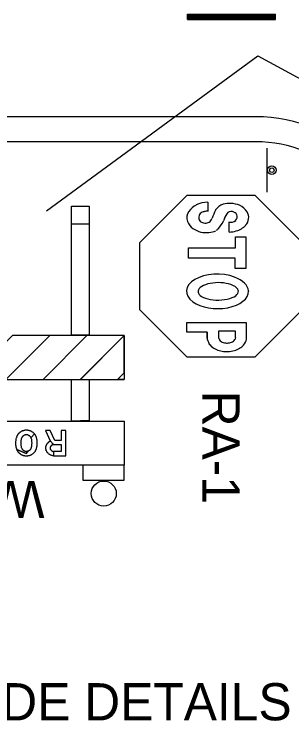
# Model space of a CAD drawing. Extents: x 1482 to 1692, y 225 to 494.
# Drawn here: x 1523.34 to 1536.77, y 348.19 to 382.4 of the extents above; entities that cross this region are included whole.
import ezdxf

# ---------------------------------------------------------------- set-up
doc = ezdxf.new("R2010")
doc.units = 0
doc.layers.add('Level 17', color=7, linetype='Continuous')
doc.layers.add('Level 2', color=7, linetype='Continuous')

msp = doc.modelspace()

# ---------------------------------------------------------------- linework, layer by layer
at = {"layer": 'Level 17'}
for p, q in [((1524.905, 372.882), (1535.123, 380.389)), ((1535.123, 380.389), (1542.24, 376.488)), ((1535.565, 375.918), (1535.565, 373.784)), ((1532.709, 373.304), (1532.709, 372.854)), ((1532.14, 373.162), (1532.142, 373.165)), ((1533.741, 371.848), (1533.741, 372.34)), ((1526.117, 372.257), (1526.968, 372.257)), ((1534.041, 371.086), (1534.041, 371.614)), ((1534.041, 371.614), (1534.544, 371.614)), ((1534.544, 371.614), (1534.544, 370.084)), ((1531.78, 370.588), (1531.78, 371.086)), ((1531.78, 371.086), (1534.041, 371.086)), ((1534.029, 370.588), (1531.78, 370.588)), ((1534.029, 370.084), (1534.029, 370.588)), ((1534.544, 370.084), (1534.029, 370.084)), ((1534.182, 369.026), (1534.186, 369.007)), ((1534.671, 369.007), (1534.672, 368.992)), ((1531.696, 367.003), (1531.696, 367.48)), ((1531.696, 367.48), (1534.57, 367.48)), ((1534.57, 367.48), (1534.57, 366.676)), ((1528.668, 366.838), (1528.668, 364.713)), ((1532.676, 367.003), (1531.696, 367.003)), ((1532.676, 367.003), (1532.676, 366.703)), ((1532.684, 366.716), (1532.676, 367.003)), ((1534.054, 367.06), (1533.219, 367.06)), ((1533.219, 367.06), (1533.219, 366.754)), ((1534.054, 367.06), (1533.219, 367.06)), ((1533.219, 367.06), (1533.219, 366.754)), ((1534.054, 366.748), (1534.054, 367.06)), ((1534.054, 366.748), (1534.054, 367.06)), ((1507.928, 364.713), (1528.668, 364.713)), ((1507.928, 362.695), (1528.668, 362.695)), ((1528.668, 362.695), (1528.668, 360.57)), ((1524.162, 361.903), (1524.327, 362.077)), ((1524.327, 362.077), (1524.162, 361.903)), ((1524.172, 361.874), (1524.162, 361.903)), ((1525.092, 361.739), (1525.247, 361.565)), ((1525.092, 361.739), (1525.247, 361.565)), ((1523.477, 361.323), (1523.93, 361.136)), ((1523.93, 361.136), (1523.477, 361.323)), ((1525.247, 361.565), (1525.256, 361.565)), ((1523.93, 361.136), (1524.018, 361.256)), ((1524.018, 361.256), (1523.93, 361.136)), ((1525.247, 361.236), (1525.247, 361.024)), ((1525.247, 361.236), (1525.247, 361.024)), ((1528.668, 360.57), (1507.928, 360.57))]:
    msp.add_line(p, q, dxfattribs=at)
for points in [[(1531.716, 365.791), (1529.422, 368.084), (1529.422, 371.352), (1531.716, 373.645), (1534.983, 373.645), (1537.275, 371.352), (1537.275, 368.084), (1534.983, 365.791)], [(1526.968, 366.86), (1526.117, 366.86), (1526.117, 373.108), (1526.968, 373.108)], [(1521.134, 364.713), (1522.938, 364.713), (1525.063, 366.838), (1523.259, 366.838)], [(1524.74, 364.713), (1526.544, 364.713), (1528.669, 366.838), (1526.865, 366.838)], [(1528.668, 364.713), (1528.346, 364.713), (1528.668, 365.035)], [(1526.968, 362.737), (1526.117, 362.695), (1526.117, 364.713), (1526.968, 364.713)], [(1528.668, 360.57), (1526.664, 360.57), (1526.664, 359.842), (1528.668, 359.842)]]:
    msp.add_lwpolyline(points, close=True, dxfattribs=at)
for points in [[(1525.062, 366.838), (1522.937, 364.713), (1524.74, 364.713), (1526.865, 366.838), (1525.062, 366.838)], [(1528.668, 366.838), (1526.543, 364.713), (1528.346, 364.713), (1528.668, 365.035), (1528.668, 366.838)], [(1523.477, 361.323), (1523.467, 361.352), (1523.457, 361.372), (1523.457, 361.401), (1523.448, 361.43), (1523.448, 361.449), (1523.438, 361.478), (1523.438, 361.497), (1523.428, 361.526), (1523.428, 361.555), (1523.428, 361.575), (1523.428, 361.603), (1523.428, 361.632), (1523.428, 361.652), (1523.428, 361.681), (1523.428, 361.7), (1523.428, 361.729), (1523.438, 361.758), (1523.438, 361.777), (1523.438, 361.806), (1523.448, 361.835), (1523.448, 361.855), (1523.457, 361.884), (1523.457, 361.893), (1523.467, 361.913), (1523.467, 361.932), (1523.477, 361.951), (1523.486, 361.961), (1523.486, 361.98), (1523.496, 361.999), (1523.506, 362.009), (1523.515, 362.028), (1523.525, 362.048), (1523.535, 362.057), (1523.544, 362.077), (1523.554, 362.086), (1523.564, 362.096), (1523.573, 362.115), (1523.593, 362.125), (1523.602, 362.135), (1523.612, 362.154), (1523.631, 362.164), (1523.641, 362.173), (1523.66, 362.183), (1523.67, 362.192), (1523.689, 362.202), (1523.699, 362.212), (1523.718, 362.222), (1523.738, 362.231), (1523.747, 362.231), (1523.766, 362.241), (1523.786, 362.25), (1523.805, 362.25), (1523.815, 362.26), (1523.834, 362.26), (1523.853, 362.26), (1523.873, 362.27), (1523.892, 362.27), (1523.902, 362.27), (1523.921, 362.27), (1523.94, 362.27), (1523.96, 362.27), (1523.979, 362.27), (1523.989, 362.27), (1524.008, 362.26), (1524.027, 362.26), (1524.047, 362.26), (1524.066, 362.25), (1524.076, 362.25), (1524.095, 362.241), (1524.114, 362.241), (1524.134, 362.231), (1524.143, 362.222), (1524.162, 362.212), (1524.182, 362.202), (1524.191, 362.192), (1524.211, 362.183), (1524.22, 362.173), (1524.239, 362.164), (1524.249, 362.154), (1524.259, 362.144), (1524.278, 362.135), (1524.288, 362.115), (1524.298, 362.106), (1524.307, 362.096), (1524.327, 362.077)], [(1524.327, 362.077), (1524.336, 362.067), (1524.346, 362.048), (1524.356, 362.038), (1524.365, 362.019), (1524.375, 361.999), (1524.375, 361.99), (1524.385, 361.971), (1524.394, 361.951), (1524.404, 361.932), (1524.404, 361.903), (1524.414, 361.884), (1524.423, 361.855), (1524.423, 361.826), (1524.433, 361.806), (1524.433, 361.777), (1524.433, 361.758), (1524.443, 361.729), (1524.443, 361.7), (1524.443, 361.681), (1524.443, 361.652), (1524.443, 361.623), (1524.443, 361.594), (1524.443, 361.575), (1524.443, 361.545), (1524.433, 361.516), (1524.433, 361.497), (1524.433, 361.468), (1524.423, 361.449), (1524.423, 361.42), (1524.414, 361.391), (1524.404, 361.372), (1524.404, 361.343), (1524.394, 361.323), (1524.385, 361.304), (1524.375, 361.285), (1524.375, 361.275), (1524.365, 361.256), (1524.356, 361.236), (1524.346, 361.227), (1524.336, 361.207), (1524.327, 361.198), (1524.307, 361.179), (1524.298, 361.169), (1524.288, 361.159), (1524.278, 361.14), (1524.259, 361.13), (1524.249, 361.12), (1524.239, 361.111), (1524.22, 361.101), (1524.211, 361.092), (1524.191, 361.082), (1524.182, 361.072), (1524.162, 361.062), (1524.143, 361.053), (1524.134, 361.043), (1524.114, 361.033), (1524.095, 361.033), (1524.076, 361.024), (1524.066, 361.024), (1524.047, 361.014), (1524.027, 361.014), (1524.008, 361.014), (1523.989, 361.005), (1523.979, 361.005), (1523.96, 361.005), (1523.94, 361.005), (1523.921, 361.005), (1523.902, 361.005), (1523.882, 361.005), (1523.873, 361.005), (1523.853, 361.014), (1523.834, 361.014), (1523.815, 361.014), (1523.795, 361.024), (1523.786, 361.033), (1523.766, 361.033), (1523.747, 361.043), (1523.738, 361.043), (1523.718, 361.053), (1523.699, 361.062), (1523.689, 361.072), (1523.67, 361.082), (1523.66, 361.092), (1523.641, 361.101), (1523.631, 361.111), (1523.612, 361.12), (1523.602, 361.14), (1523.593, 361.149), (1523.573, 361.159), (1523.564, 361.179), (1523.554, 361.188), (1523.544, 361.198), (1523.535, 361.217), (1523.525, 361.227), (1523.515, 361.246), (1523.506, 361.265), (1523.496, 361.275), (1523.486, 361.294), (1523.486, 361.314), (1523.477, 361.323)], [(1524.172, 361.874), (1524.162, 361.884), (1524.162, 361.903), (1524.153, 361.913), (1524.143, 361.922), (1524.134, 361.932), (1524.134, 361.942), (1524.124, 361.951), (1524.114, 361.961), (1524.105, 361.971), (1524.095, 361.98), (1524.085, 361.99), (1524.076, 361.99), (1524.056, 361.999), (1524.047, 362.009), (1524.037, 362.009), (1524.027, 362.019), (1524.018, 362.019), (1523.998, 362.028), (1523.989, 362.028), (1523.979, 362.028), (1523.96, 362.028), (1523.95, 362.028), (1523.94, 362.038), (1523.921, 362.038), (1523.911, 362.028), (1523.902, 362.028), (1523.882, 362.028), (1523.873, 362.028), (1523.863, 362.019), (1523.853, 362.019), (1523.834, 362.019), (1523.824, 362.009), (1523.815, 361.999), (1523.805, 361.999), (1523.795, 361.99), (1523.786, 361.98), (1523.776, 361.971), (1523.766, 361.971), (1523.757, 361.961), (1523.747, 361.951), (1523.738, 361.942), (1523.728, 361.922), (1523.718, 361.913), (1523.718, 361.903), (1523.709, 361.893), (1523.699, 361.884), (1523.699, 361.874), (1523.689, 361.845), (1523.689, 361.826), (1523.68, 361.806), (1523.68, 361.787), (1523.67, 361.758), (1523.67, 361.739), (1523.67, 361.719), (1523.67, 361.69), (1523.66, 361.671), (1523.66, 361.652), (1523.66, 361.623), (1523.66, 361.603), (1523.67, 361.584), (1523.67, 361.555), (1523.67, 361.536), (1523.67, 361.516), (1523.68, 361.488), (1523.68, 361.468), (1523.689, 361.449), (1523.689, 361.43), (1523.689, 361.42), (1523.699, 361.41), (1523.699, 361.401), (1523.709, 361.381), (1523.709, 361.372), (1523.718, 361.362), (1523.728, 361.352), (1523.738, 361.343), (1523.738, 361.333), (1523.747, 361.323), (1523.757, 361.314), (1523.766, 361.304), (1523.776, 361.294), (1523.786, 361.285), (1523.795, 361.285), (1523.805, 361.275), (1523.824, 361.265), (1523.834, 361.265), (1523.844, 361.256), (1523.853, 361.256), (1523.863, 361.246), (1523.882, 361.246), (1523.892, 361.246), (1523.902, 361.246), (1523.921, 361.246), (1523.931, 361.236), (1523.94, 361.236), (1523.96, 361.246), (1523.969, 361.246), (1523.979, 361.246), (1523.998, 361.246), (1524.008, 361.256), (1524.018, 361.256)], [(1525.247, 361.024), (1525.836, 361.024), (1525.836, 362.25), (1525.624, 362.25), (1525.624, 361.768), (1525.315, 361.768), (1525.092, 362.25), (1524.861, 362.25), (1525.092, 361.739)], [(1524.018, 361.256), (1524.027, 361.256), (1524.047, 361.265), (1524.056, 361.275), (1524.066, 361.275), (1524.076, 361.285), (1524.085, 361.294), (1524.095, 361.294), (1524.105, 361.304), (1524.114, 361.314), (1524.124, 361.323), (1524.134, 361.333), (1524.143, 361.343), (1524.143, 361.352), (1524.153, 361.362), (1524.162, 361.381), (1524.162, 361.391), (1524.172, 361.401), (1524.172, 361.41), (1524.182, 361.43), (1524.182, 361.439), (1524.182, 361.449), (1524.191, 361.478), (1524.191, 361.497), (1524.201, 361.516), (1524.201, 361.536), (1524.201, 361.565), (1524.201, 361.584), (1524.201, 361.603), (1524.211, 361.632), (1524.211, 361.652), (1524.201, 361.681), (1524.201, 361.7), (1524.201, 361.719), (1524.201, 361.748), (1524.191, 361.768), (1524.191, 361.787), (1524.191, 361.806), (1524.182, 361.835), (1524.172, 361.855), (1524.172, 361.874)], [(1525.256, 361.024), (1525.237, 361.024), (1525.218, 361.024), (1525.208, 361.024), (1525.189, 361.033), (1525.17, 361.033), (1525.16, 361.033), (1525.141, 361.043), (1525.131, 361.043), (1525.112, 361.053), (1525.102, 361.053), (1525.083, 361.062), (1525.073, 361.072), (1525.063, 361.082), (1525.044, 361.082), (1525.034, 361.092), (1525.025, 361.101), (1525.005, 361.111), (1524.996, 361.12), (1524.986, 361.14), (1524.976, 361.149), (1524.967, 361.159), (1524.957, 361.169), (1524.947, 361.179), (1524.938, 361.198), (1524.928, 361.207), (1524.918, 361.227), (1524.918, 361.236), (1524.909, 361.256), (1524.899, 361.265), (1524.899, 361.285), (1524.889, 361.294), (1524.889, 361.314), (1524.889, 361.323), (1524.88, 361.343), (1524.88, 361.352), (1524.88, 361.372), (1524.88, 361.391), (1524.88, 361.401), (1524.88, 361.42), (1524.88, 361.43), (1524.88, 361.449), (1524.88, 361.468), (1524.889, 361.478), (1524.889, 361.497), (1524.899, 361.507), (1524.899, 361.526), (1524.909, 361.536), (1524.909, 361.555), (1524.918, 361.565), (1524.928, 361.584), (1524.938, 361.594), (1524.938, 361.603), (1524.947, 361.623), (1524.957, 361.632), (1524.967, 361.642), (1524.986, 361.652), (1524.996, 361.671), (1525.005, 361.681), (1525.015, 361.69), (1525.025, 361.7), (1525.044, 361.71), (1525.053, 361.719), (1525.063, 361.719), (1525.083, 361.729), (1525.092, 361.739)], [(1525.256, 361.565), (1525.237, 361.565), (1525.228, 361.555), (1525.218, 361.555), (1525.208, 361.555), (1525.199, 361.555), (1525.189, 361.545), (1525.179, 361.545), (1525.17, 361.536), (1525.16, 361.536), (1525.16, 361.526), (1525.15, 361.526), (1525.141, 361.516), (1525.131, 361.507), (1525.131, 361.497), (1525.121, 361.497), (1525.112, 361.488), (1525.112, 361.478), (1525.102, 361.468), (1525.102, 361.459), (1525.092, 361.449), (1525.092, 361.439), (1525.092, 361.43), (1525.092, 361.42), (1525.092, 361.41), (1525.092, 361.401), (1525.092, 361.391), (1525.092, 361.381), (1525.092, 361.372), (1525.092, 361.362), (1525.092, 361.343), (1525.102, 361.333), (1525.112, 361.323), (1525.112, 361.314), (1525.121, 361.304), (1525.131, 361.294), (1525.131, 361.285), (1525.141, 361.275), (1525.15, 361.275), (1525.16, 361.265), (1525.16, 361.256), (1525.17, 361.256), (1525.179, 361.246), (1525.189, 361.246), (1525.199, 361.246), (1525.208, 361.236), (1525.218, 361.236), (1525.228, 361.236), (1525.237, 361.236), (1525.247, 361.236)], [(1525.247, 361.565), (1525.624, 361.565), (1525.624, 361.236), (1525.247, 361.236)]]:
    msp.add_lwpolyline(points, dxfattribs=at)
for centre, radius in [((1535.804, 374.847), 0.213), ((1535.804, 374.847), 0.107), ((1527.677, 359.194), 0.606)]:
    msp.add_circle(centre, radius, dxfattribs=at)
for centre, radius, start, end in [((1532.776, 371.803), 1.502, 92.3841, 114.9519), ((1532.65, 372.221), 1.07, 118.4154, 143.6553), ((1533.709, 372.485), 0.762, 110.4481, 145.1107), ((1533.74, 372.171), 1.071, 84.8171, 105.9183), ((1533.774, 372.02), 1.219, 67.7332, 87.1392), ((1533.879, 372.354), 0.87, 33.3662, 65.6734), ((1532.173, 372.554), 0.489, 142.0536, 202.7397), ((1532.603, 372.543), 0.335, 140.6966, 181.4573), ((1532.572, 372.497), 0.344, 96.8728, 132.7449), ((1532.701, 372.175), 0.685, 89.0172, 103.5172), ((1538.061, 370.533), 5.521, 154.4624, 158.8312), ((1535.052, 371.847), 1.68, 147.9816, 160.979), ((1533.833, 372.61), 0.242, 74.131, 148.1476), ((1533.871, 372.579), 0.264, 23.8064, 82.2407), ((1533.85, 372.6), 0.277, 317.3017, 19.0119), ((1534.153, 372.554), 0.532, 316.1369, 31.3987), ((1532.438, 372.669), 0.782, 203.1413, 234.9906), ((1532.577, 372.568), 0.31, 185.4374, 224.0625), ((1532.575, 372.703), 0.413, 236.253, 268.7323), ((1532.613, 372.607), 0.319, 262.5761, 300.4776), ((1532.576, 372.617), 0.348, 304.2083, 344.1552), ((1532.374, 372.833), 1.175, 316.2465, 337.9263), ((1533.801, 372.729), 0.405, 260.4412, 309.3244), ((1532.761, 373.15), 1.361, 235.5092, 253.2894), ((1534.523, 370.432), 2.053, 129.479, 133.426), ((1533.861, 372.776), 0.898, 284.564, 319.0063), ((1532.641, 373.556), 1.731, 261.247, 273.9864), ((1532.637, 373.046), 1.223, 275.9097, 291.9865), ((1533.719, 373.094), 1.243, 270.6952, 287.1452), ((1532.846, 366.687), 0.166, 169.7909, 203.5419), ((1533.369, 366.829), 0.706, 196.602, 209.8091), ((1533.186, 366.686), 0.478, 205.3838, 232.6188), ((1533.537, 366.82), 0.325, 191.9191, 235.7868), ((1533.537, 366.82), 0.325, 191.9191, 235.7868), ((1533.585, 366.9), 0.418, 236.5086, 267.0313), ((1533.585, 366.9), 0.418, 236.5086, 267.0313), ((1533.641, 366.944), 0.468, 260.3417, 285.2342), ((1533.641, 366.944), 0.468, 260.3417, 285.2342), ((1533.698, 366.928), 0.44, 278.6031, 304.217), ((1533.698, 366.928), 0.44, 278.6031, 304.217), ((1533.783, 366.796), 0.283, 305.1198, 349.3117), ((1533.783, 366.796), 0.283, 305.1198, 349.3117), ((1534.098, 366.718), 0.477, 314.8528, 355.0441), ((1533.408, 366.887), 0.774, 228.2922, 248.6031), ((1533.408, 366.887), 0.774, 228.2922, 248.6031), ((1533.712, 367.642), 1.588, 248.3153, 258.6699), ((1533.587, 367.576), 1.512, 273.3903, 285.6597), ((1533.817, 366.878), 0.778, 283.0674, 303.762), ((1533.888, 366.868), 0.732, 299.2241, 318.5308), ((1533.888, 366.868), 0.732, 299.2241, 318.5308), ((1533.617, 367.28), 1.215, 259.7521, 272.7916), ((1533.617, 367.28), 1.215, 259.7521, 272.7916)]:
    msp.add_arc(centre, radius, start, end, dxfattribs=at)
for centre, major_axis, ratio, start_param, end_param in [((1533.175, 368.98), (-1.497, 0.01), 0.558644, 4.129576, 6.939747), ((1533.175, 368.98), (-1.497, 0.01), 0.558644, 3.185857, 4.129398), ((1533.21, 368.98), (-0.977, -0.005), 0.432619, 3.890436, 7.165085), ((1533.21, 368.98), (-0.977, -0.005), 0.432619, 3.239639, 3.888884), ((1533.175, 368.98), (-1.497, 0.01), 0.558644, 0.656861, 3.168126), ((1533.21, 368.98), (-0.977, -0.005), 0.432619, 0.881967, 3.190734)]:
    msp.add_ellipse(centre, major_axis=major_axis, ratio=ratio, start_param=start_param, end_param=end_param, dxfattribs=at)
at = {"layer": 'Level 2'}
for p, q in [((1531.72, 382.403), (1535.986, 382.403)), ((1531.72, 382.147), (1531.72, 382.403)), ((1531.72, 382.339), (1535.986, 382.339)), ((1531.72, 382.275), (1535.986, 382.275)), ((1531.72, 382.211), (1535.986, 382.211)), ((1535.986, 382.147), (1535.986, 382.403)), ((1531.72, 382.147), (1535.986, 382.147)), ((1535.032, 377.436), (1503.354, 377.436)), ((1535.032, 376.227), (1503.354, 376.227))]:
    msp.add_line(p, q, dxfattribs=at)
for radius in [7.258, 6.048]:
    msp.add_arc((1535.032, 370.179), radius, 0, 90, dxfattribs=at)

# ---------------------------------------------------------------- texts
at = {"layer": 'Level 17'}
for s, height, rotation, p in [('RA-1', 1.8, 270, (1532.446, 364.171)), ('WD-116-2', 1.8, 180, (1524.812, 359.807)), ('FOR BARRICADE DETAILS', 1.79999, 360, (1506.267, 348.213))]:
    msp.add_text(s, height=height, rotation=rotation, dxfattribs=at).set_placement(p)

doc.saveas('drawing.dxf')
